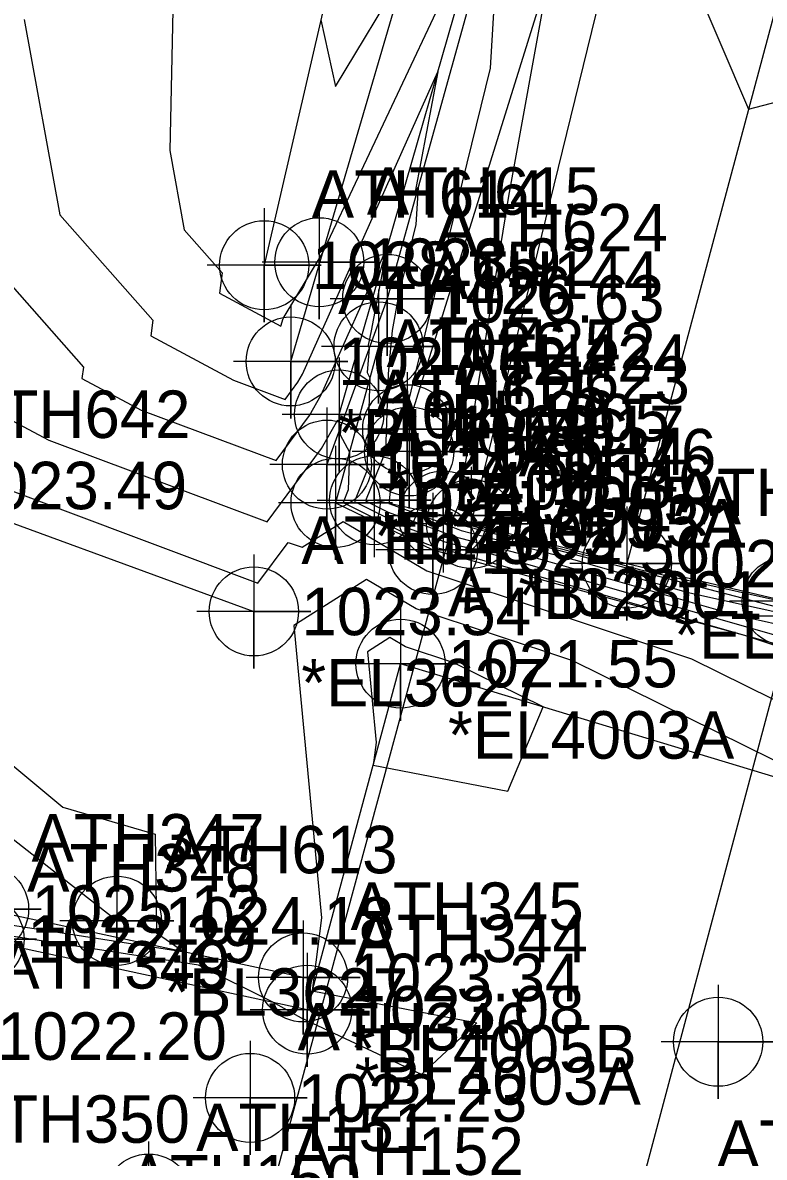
# Model space of a CAD drawing. Extents: x 1213164 to 1213550, y 766120 to 766870.
# Drawn here: x 1213304.4 to 1213343.4, y 766479.8 to 766539.5 of the extents above; entities that cross this region are included whole.
import ezdxf

# ---------------------------------------------------------------- set-up
doc = ezdxf.new("R2010")
doc.units = 0
for name, color, linetype in [('Default', 7, 'Continuous'), ('Exist DTM Breakline', 7, 'Continuous'), ('Exist DTM Breakline Cogo Comment', 7, 'Continuous'), ('Exist DTM Breakline Cogo Elevation', 7, 'Continuous'), ('Exist DTM Breakline Cogo Number', 7, 'Continuous'), ('Exist DTM Breakline Cogo Point CELL', 7, 'Continuous'), ('Exist DTM Crownline', 7, 'Continuous'), ('Exist DTM Crownline Cogo Comment', 7, 'Continuous'), ('Exist DTM Crownline Cogo Elevation', 7, 'Continuous'), ('Exist DTM Crownline Cogo Number', 7, 'Continuous'), ('Exist DTM Crownline Cogo Point CELL', 7, 'Continuous'), ('Exist DTM Drainline Cogo Comment', 7, 'Continuous'), ('Exist DTM Drainline Cogo Elevation', 7, 'Continuous'), ('Exist DTM Drainline Cogo Number', 7, 'Continuous'), ('Exist DTM Drainline Cogo Point CELL', 7, 'Continuous'), ('Exist DTM Regular Point Underwater CELL', 7, 'Continuous'), ('Exist DTM Regular Point Underwater Cogo Elevation', 7, 'Continuous'), ('Exist DTM Regular Point Underwater Cogo Number', 7, 'Continuous'), ('Exist Environmental Wetland Boundary Cogo Comment', 7, 'Continuous'), ('Exist Environmental Wetland Boundary Cogo Elevation', 7, 'Continuous'), ('Exist Environmental Wetland Boundary Cogo Number', 7, 'Continuous'), ('Exist Environmental Wetland Boundary Cogo Point CELL', 7, 'Continuous'), ('Exist Hydro Stream or Body of Water', 7, 'Continuous'), ('Exist Roads EOP', 7, 'Continuous'), ('Exist Roads EOP Cogo Comment', 7, 'Continuous'), ('Exist Roads EOP Cogo Elevation', 7, 'Continuous'), ('Exist Roads EOP Cogo Number', 7, 'Continuous'), ('Exist Roads EOP Cogo Point CELL', 7, 'Continuous'), ('Exist Structure Major Bridge WW Cogo Point CELL', 7, 'Continuous'), ('Exist Structure Major Deck Tunnel Box Culvert', 7, 'Continuous')]:
    doc.layers.add(name, color=color, linetype=linetype)

msp = doc.modelspace()

# ---------------------------------------------------------------- linework, layer by layer
at = {"layer": 'Default'}
for points in [[(1213312.606, 766556.566), (1213312.101, 766532.787), (1213312.865, 766528.603), (1213314.862, 766526.342), (1213314.71, 766525.28), (1213317.951, 766523.549), (1213318.074, 766523.952), (1213320.124, 766527.347), (1213326.276, 766540.392)], [(1213338.026, 766545.563), (1213342.554, 766534.959), (1213352.005, 766537.439), (1213352.534, 766537.592), (1213352.635, 766537.795), (1213353.026, 766538.706), (1213360.065, 766554.633)], [(1213332.007, 766541.892), (1213329.931, 766530.39), (1213327.288, 766514.12), (1213327, 766513.422), (1213327.863, 766513.073), (1213335.576, 766511.086), (1213336.81, 766510.732), (1213344.6, 766509), (1213344.738, 766508.974), (1213344.969, 766509.109), (1213352.579, 766524.276), (1213353.118, 766525.201), (1213353.296, 766525.429), (1213353.142, 766525.661), (1213361.519, 766549.652)], [(1213329.521, 766546.518), (1213328.953, 766537.116), (1213324.533, 766519.114), (1213324.485, 766518.851), (1213324.455, 766518.529), (1213324.436, 766517.95), (1213323.889, 766516.593), (1213323.629, 766514.207), (1213326.375, 766513.206), (1213327.431, 766512.78), (1213333.408, 766511.239), (1213339.3, 766509.55), (1213345.088, 766508.264), (1213346.155, 766508.062), (1213347.253, 766507.894), (1213348.774, 766508.818), (1213350.878, 766509.604), (1213350.411, 766509.881), (1213356.086, 766519.612), (1213359.141, 766523.529), (1213356.49, 766527.5), (1213362.202, 766543.858)], [(1213320.053, 766539.664), (1213320.823, 766536.156), (1213324.495, 766542.241)], [(1213304.44, 766539.672), (1213306.316, 766529.407), (1213311.215, 766523.86), (1213311.097, 766523.033), (1213315.452, 766520.706), (1213318.168, 766519.688), (1213318.845, 766520.601), (1213319.079, 766521.012), (1213326.207, 766536.928), (1213325.007, 766530.61), (1213325.17, 766530.84), (1213325.052, 766528.892), (1213324.137, 766525.162), (1213323.799, 766523.309), (1213323.589, 766521.031), (1213323.455, 766516.943), (1213322.408, 766514.347), (1213323.588, 766513.758), (1213326.249, 766512.788), (1213326.998, 766512.486), (1213331.241, 766511.392), (1213341.791, 766508.368), (1213345.575, 766507.527)], [(1213299.767, 766530.211), (1213307.568, 766521.377), (1213307.483, 766520.786), (1213310.597, 766519.123), (1213317.694, 766516.463), (1213319.461, 766518.848), (1213320.073, 766519.922), (1213323.53, 766527.642), (1213322.704, 766523.294), (1213322.531, 766522.548), (1213322.601, 766522.383), (1213322.486, 766521.1), (1213322.634, 766520.829), (1213322.474, 766515.935), (1213321.817, 766514.308), (1213324.551, 766512.944), (1213326.123, 766512.37), (1213326.566, 766512.192), (1213329.073, 766511.545), (1213344.281, 766507.187)], [(1213302.238, 766492.24), (1213291.887, 766494.194), (1213280.351, 766496.799), (1213269.143, 766496.101), (1213258.434, 766495.354), (1213246.448, 766501.682), (1213231.43, 766508.485), (1213230.134, 766509.143), (1213229.018, 766509.648), (1213227.82, 766526.686), (1213231.745, 766525.976), (1213232.384, 766525.606), (1213255.391, 766521.519), (1213260.994, 766517.838), (1213268.066, 766515.14), (1213276.814, 766515.993), (1213284.275, 766516.118), (1213289.429, 766512.414), (1213289.748, 766512.148), (1213306.473, 766498.233), (1213311.338, 766496.807), (1213311.406, 766491.611), (1213312.871, 766490.604), (1213302.238, 766492.24)], [(1213303.87, 766518.54), (1213305.741, 766517.54), (1213317.218, 766513.237), (1213320.077, 766517.095), (1213320.94, 766518.61), (1213321.096, 766518.242), (1213321.058, 766517.826), (1213321.557, 766516.911), (1213321.492, 766514.928), (1213321.226, 766514.269), (1213325.513, 766512.129), (1213325.997, 766511.953), (1213326.133, 766511.898), (1213326.906, 766511.699), (1213342.392, 766507.26), (1213345.801, 766506.125), (1213346.659, 766505.701), (1213349.337, 766501.052), (1213351.669, 766499.048), (1213357.648, 766493.804), (1213369.246, 766482.036), (1213370.687, 766479.709)], [(1213300.885, 766515.957), (1213316.743, 766510.012), (1213318.331, 766512.154), (1213319.064, 766511.902), (1213321.218, 766513.267), (1213325.627, 766510.661), (1213339.551, 766506.025), (1213348.137, 766501.785), (1213349.431, 766499.539), (1213350.558, 766498.57), (1213361.343, 766489.111), (1213368.811, 766481.534), (1213374.658, 766472.092), (1213383.401, 766456.504), (1213384.24, 766453.245), (1213389.563, 766440.166), (1213389.659, 766438.461), (1213389.891, 766435.088), (1213390.675, 766420.964), (1213391.789, 766405.168), (1213396.624, 766394.628)], [(1213378.629, 766464.474), (1213368.376, 766481.032), (1213365.038, 766484.419), (1213350.897, 766496.821), (1213346.478, 766493.776), (1213348.434, 766498.453), (1213333.3, 766505.924), (1213325.062, 766508.667), (1213322.453, 766510.209), (1213318.62, 766507.782), (1213320.087, 766492.397), (1213319.595, 766488.556), (1213328.26, 766486.873), (1213325.345, 766484.153), (1213319.036, 766487.115), (1213317.521, 766487.959), (1213313.605, 766489.92), (1213302.155, 766491.681)], [(1213329.881, 766499.067), (1213331.739, 766503.509), (1213327.05, 766505.824), (1213324.497, 766506.674), (1213323.688, 766507.152), (1213322.501, 766506.4), (1213322.955, 766501.632), (1213322.803, 766500.442), (1213329.881, 766499.067)]]:
    msp.add_lwpolyline(points, dxfattribs=at)
at = {"layer": 'Exist DTM Breakline'}
msp.add_line((1213326.487, 766513.577), (1213322.857, 766514.377), dxfattribs=at)
for points in [[(1213233.323, 766620.634), (1213306.317, 766606.349), (1213329.347, 766592.96), (1213324.12, 766557.271), (1213317.07, 766526.747)], [(1213318.463, 766521.688), (1213327.406, 766552.16), (1213336.347, 766594.126)], [(1213340.32, 766592.831), (1213332.04, 766555.596), (1213323.543, 766524.976), (1213320.373, 766516.254)], [(1213321.009, 766518.895), (1213330.265, 766551.006), (1213340.105, 766593.056)], [(1213324.598, 766518.116), (1213334.42, 766549.638), (1213342.103, 766590.629)], [(1213323.087, 766522.479), (1213320.824, 766514.242), (1213325.941, 766511.767), (1213346.495, 766506.136), (1213349.294, 766501.74), (1213353.051, 766499.642)], [(1213319.115, 766489.266), (1213302.33, 766492.864), (1213279.67, 766497.667), (1213258.903, 766496.781), (1213229.457, 766510.311)]]:
    msp.add_lwpolyline(points, dxfattribs=at)
at = {"layer": 'Exist DTM Breakline Cogo Point CELL'}
for points in [[(1213317.07, 766529.747), (1213317.07, 766523.747), (1213317.07, 766526.747), (1213320.07, 766526.747), (1213314.07, 766526.747)], [(1213319.97, 766529.906), (1213319.97, 766523.906), (1213319.97, 766526.906), (1213322.97, 766526.906), (1213316.97, 766526.906)], [(1213323.543, 766527.976), (1213323.543, 766521.976), (1213323.543, 766524.976), (1213326.543, 766524.976), (1213320.543, 766524.976)], [(1213323.087, 766525.479), (1213323.087, 766519.479), (1213323.087, 766522.479), (1213326.087, 766522.479), (1213320.087, 766522.479)], [(1213318.463, 766524.688), (1213318.463, 766518.688), (1213318.463, 766521.688), (1213321.463, 766521.688), (1213315.463, 766521.688)], [(1213321.009, 766521.895), (1213321.009, 766515.895), (1213321.009, 766518.895), (1213324.009, 766518.895), (1213318.009, 766518.895)], [(1213324.598, 766521.116), (1213324.598, 766515.116), (1213324.598, 766518.116), (1213327.598, 766518.116), (1213321.598, 766518.116)], [(1213324.699, 766519.95), (1213324.699, 766513.95), (1213324.699, 766516.95), (1213327.699, 766516.95), (1213321.699, 766516.95)], [(1213320.373, 766519.254), (1213320.373, 766513.254), (1213320.373, 766516.254), (1213323.373, 766516.254), (1213317.373, 766516.254)], [(1213320.824, 766517.242), (1213320.824, 766511.242), (1213320.824, 766514.242), (1213323.824, 766514.242), (1213317.824, 766514.242)], [(1213325.941, 766514.767), (1213325.941, 766508.767), (1213325.941, 766511.767), (1213328.941, 766511.767), (1213322.941, 766511.767)], [(1213302.33, 766495.864), (1213302.33, 766489.864), (1213302.33, 766492.864), (1213305.33, 766492.864), (1213299.33, 766492.864)], [(1213319.115, 766492.266), (1213319.115, 766486.266), (1213319.115, 766489.266), (1213322.115, 766489.266), (1213316.115, 766489.266)], [(1213310.985, 766480.629), (1213310.985, 766474.629), (1213310.985, 766477.629), (1213313.985, 766477.629), (1213307.985, 766477.629)]]:
    msp.add_lwpolyline(points, dxfattribs=at)
for centre in [(1213317.07, 766526.747), (1213319.97, 766526.906), (1213323.543, 766524.976), (1213323.087, 766522.479), (1213318.463, 766521.688), (1213321.009, 766518.895), (1213324.598, 766518.116), (1213324.699, 766516.95), (1213320.373, 766516.254), (1213320.824, 766514.242), (1213325.941, 766511.767), (1213302.33, 766492.864), (1213319.115, 766489.266), (1213310.985, 766477.629)]:
    msp.add_circle(centre, 2.344, dxfattribs=at)
at = {"layer": 'Exist DTM Crownline'}
msp.add_lwpolyline([(1213369.874, 766637.44), (1213360.318, 766601.875), (1213348.565, 766557.408), (1213336.15, 766511.045)], dxfattribs=at)
at = {"layer": 'Exist DTM Crownline Cogo Point CELL'}
msp.add_lwpolyline([(1213336.15, 766514.045), (1213336.15, 766508.045), (1213336.15, 766511.045), (1213339.15, 766511.045), (1213333.15, 766511.045)], dxfattribs=at)
msp.add_circle((1213336.15, 766511.045), 2.344, dxfattribs=at)
at = {"layer": 'Exist DTM Drainline Cogo Point CELL'}
for points in [[(1213324.243, 766508.779), (1213324.243, 766502.779), (1213324.243, 766505.779), (1213327.243, 766505.779), (1213321.243, 766505.779)], [(1213302.096, 766494.285), (1213302.096, 766488.285), (1213302.096, 766491.285), (1213305.096, 766491.285), (1213299.096, 766491.285)], [(1213319.329, 766490.569), (1213319.329, 766484.569), (1213319.329, 766487.569), (1213322.329, 766487.569), (1213316.329, 766487.569)]]:
    msp.add_lwpolyline(points, dxfattribs=at)
for centre in [(1213324.243, 766505.779), (1213302.096, 766491.285), (1213319.329, 766487.569)]:
    msp.add_circle(centre, 2.344, dxfattribs=at)
at = {"layer": 'Exist DTM Regular Point Underwater CELL'}
for points in [[(1213340.957, 766488.883), (1213340.957, 766482.883), (1213340.957, 766485.883), (1213343.957, 766485.883), (1213337.957, 766485.883)], [(1213316.327, 766485.924), (1213316.327, 766479.924), (1213316.327, 766482.924), (1213319.327, 766482.924), (1213313.327, 766482.924)]]:
    msp.add_lwpolyline(points, dxfattribs=at)
for centre in [(1213340.957, 766485.883), (1213316.327, 766482.924)]:
    msp.add_circle(centre, 2.344, dxfattribs=at)
at = {"layer": 'Exist Environmental Wetland Boundary Cogo Point CELL'}
for points in [[(1213316.525, 766511.528), (1213316.525, 766505.528), (1213316.525, 766508.528), (1213319.525, 766508.528), (1213313.525, 766508.528)], [(1213309.319, 766495.246), (1213309.319, 766489.246), (1213309.319, 766492.246), (1213312.319, 766492.246), (1213306.319, 766492.246)]]:
    msp.add_lwpolyline(points, dxfattribs=at)
for centre in [(1213316.525, 766508.528), (1213309.319, 766492.246)]:
    msp.add_circle(centre, 2.344, dxfattribs=at)
at = {"layer": 'Exist Hydro Stream or Body of Water'}
msp.add_line((1213319.329, 766487.569), (1213324.243, 766505.779), dxfattribs=at)
for points in [[(1213231.611, 766558.456), (1213254.919, 766547.163), (1213282.877, 766532.283), (1213282.707, 766524.453), (1213298.428, 766515.156), (1213316.525, 766508.528)], [(1213309.319, 766492.246), (1213285.214, 766511.13), (1213261.681, 766524.754), (1213227.09, 766533.988)], [(1213319.329, 766487.569), (1213302.096, 766491.285), (1213281.341, 766495.538), (1213258.142, 766494.464), (1213228.572, 766508.974)], [(1213462.585, 766303.681), (1213457.242, 766280.725), (1213458.541, 766244.269), (1213446.982, 766261.332), (1213440.132, 766307.328), (1213429.645, 766367.831), (1213400.182, 766384.285), (1213389.875, 766405.51), (1213387.132, 766439.706), (1213382.822, 766456.43), (1213368.024, 766480.627), (1213349.519, 766498.124), (1213324.243, 766505.779)]]:
    msp.add_lwpolyline(points, dxfattribs=at)
at = {"layer": 'Exist Roads EOP'}
for points in [[(1213327.952, 766513.134), (1213339.553, 766560.471), (1213350.847, 766605.718), (1213360.678, 766641.433)], [(1213327.952, 766513.134), (1213336.15, 766511.045), (1213344.559, 766509.063)]]:
    msp.add_lwpolyline(points, dxfattribs=at)
at = {"layer": 'Exist Roads EOP Cogo Point CELL'}
for points in [[(1213327.952, 766516.134), (1213327.952, 766510.134), (1213327.952, 766513.134), (1213330.952, 766513.134), (1213324.952, 766513.134)], [(1213344.559, 766512.063), (1213344.559, 766506.063), (1213344.559, 766509.063), (1213347.559, 766509.063), (1213341.559, 766509.063)]]:
    msp.add_lwpolyline(points, dxfattribs=at)
for centre in [(1213327.952, 766513.134), (1213344.559, 766509.063)]:
    msp.add_circle(centre, 2.344, dxfattribs=at)
at = {"layer": 'Exist Structure Major Bridge WW Cogo Point CELL'}
for points in [[(1213319.857, 766514.377), (1213325.857, 766514.377), (1213322.857, 766514.377), (1213322.857, 766517.377), (1213322.857, 766511.377)], [(1213323.487, 766513.577), (1213329.487, 766513.577), (1213326.487, 766513.577), (1213326.487, 766516.577), (1213326.487, 766510.577)], [(1213343.114, 766508.293), (1213349.114, 766508.293), (1213346.114, 766508.293), (1213346.114, 766511.293), (1213346.114, 766505.293)]]:
    msp.add_lwpolyline(points, dxfattribs=at)
for centre in [(1213322.857, 766514.377), (1213326.487, 766513.577)]:
    msp.add_circle(centre, 2.344, dxfattribs=at)
at = {"layer": 'Exist Structure Major Deck Tunnel Box Culvert'}
msp.add_lwpolyline([(1213334.645, 766469.793), (1213316.583, 766474.725), (1213327.014, 766513.184), (1213344.974, 766508.526), (1213334.645, 766469.793)], dxfattribs=at)

# ---------------------------------------------------------------- texts
at = {"layer": 'Exist DTM Breakline Cogo Comment'}
for s, p in [('*BL4005', (1213325.587, 766517.479)), ('*BL4005C', (1213320.963, 766516.688)), ('*BL4005B', (1213323.509, 766513.895)), ('*BL4005A', (1213327.098, 766513.116)), ('*EL4005A', (1213327.199, 766511.95)), ('*EL4005', (1213322.873, 766511.254)), ('*BL4005B', (1213321.615, 766484.266))]:
    msp.add_text(s, height=2.5, dxfattribs=at).set_placement(p)
at = {"layer": 'Exist DTM Breakline Cogo Elevation'}
for s, p in [('1028.65', (1213319.57, 766525.497)), ('1028.92', (1213322.47, 766525.656)), ('1026.63', (1213326.043, 766523.726)), ('1026.42', (1213325.587, 766521.229)), ('1027.62', (1213320.963, 766520.438)), ('1025.06', (1213323.509, 766517.645)), ('1028.17', (1213327.098, 766516.866)), ('1028.34', (1213327.199, 766515.7)), ('1024.52', (1213322.873, 766515.004)), ('1024.32', (1213323.324, 766512.992)), ('1024.56', (1213328.441, 766510.517)), ('1025.12', (1213304.83, 766491.614)), ('1023.34', (1213321.615, 766488.016))]:
    msp.add_text(s, height=2.5, dxfattribs=at).set_placement(p)
at = {"layer": 'Exist DTM Breakline Cogo Number'}
for s, p in [('ATH615', (1213322.47, 766529.406)), ('ATH614', (1213319.57, 766529.247)), ('ATH624', (1213326.043, 766527.476)), ('ATH144', (1213325.587, 766524.979)), ('ATH426', (1213320.963, 766524.188)), ('ATH425', (1213323.509, 766521.395)), ('ATH424', (1213327.098, 766520.616)), ('ATH623', (1213327.199, 766519.45)), ('ATH625', (1213322.873, 766518.754)), ('ATH145', (1213323.324, 766516.742)), ('ATH146', (1213328.441, 766514.267)), ('ATH347', (1213304.83, 766495.364)), ('ATH345', (1213321.615, 766491.766)), ('ATH151', (1213313.485, 766480.129)), ('ATH152', (1213318.462, 766478.873)), ('ATH150', (1213309.883, 766477.413))]:
    msp.add_text(s, height=2.5, dxfattribs=at).set_placement(p)
at = {"layer": 'Exist DTM Crownline Cogo Comment'}
msp.add_text('*EL3008', height=2.5, dxfattribs=at).set_placement((1213338.65, 766506.045))
at = {"layer": 'Exist DTM Crownline Cogo Elevation'}
msp.add_text('1029.27', height=2.5, dxfattribs=at).set_placement((1213338.65, 766509.795))
at = {"layer": 'Exist DTM Crownline Cogo Number'}
msp.add_text('ATH106', height=2.5, dxfattribs=at).set_placement((1213338.65, 766513.545))
at = {"layer": 'Exist DTM Drainline Cogo Comment'}
for s, p in [('*EL4003A', (1213326.743, 766500.779)), ('*BL4003A', (1213321.829, 766482.569))]:
    msp.add_text(s, height=2.5, dxfattribs=at).set_placement(p)
at = {"layer": 'Exist DTM Drainline Cogo Elevation'}
for s, p in [('1021.55', (1213326.743, 766504.529)), ('1022.29', (1213304.596, 766490.035)), ('1023.08', (1213321.829, 766486.319))]:
    msp.add_text(s, height=2.5, dxfattribs=at).set_placement(p)
at = {"layer": 'Exist DTM Drainline Cogo Number'}
for s, p in [('ATH328', (1213326.743, 766508.279)), ('ATH348', (1213304.596, 766493.785)), ('ATH344', (1213321.829, 766490.069)), ('ATH350', (1213300.896, 766480.565))]:
    msp.add_text(s, height=2.5, dxfattribs=at).set_placement(p)
at = {"layer": 'Exist DTM Regular Point Underwater Cogo Elevation'}
for s, p in [('1022.20', (1213303.023, 766484.928)), ('1022.23', (1213318.827, 766481.674))]:
    msp.add_text(s, height=2.5, dxfattribs=at).set_placement(p)
at = {"layer": 'Exist DTM Regular Point Underwater Cogo Number'}
for s, p in [('ATH349', (1213303.023, 766488.678)), ('ATH346', (1213318.827, 766485.424)), ('ATH324', (1213340.892, 766479.244))]:
    msp.add_text(s, height=2.5, dxfattribs=at).set_placement(p)
at = {"layer": 'Exist Environmental Wetland Boundary Cogo Comment'}
for s, p in [('*EL3627', (1213319.025, 766503.528)), ('*BL3627', (1213311.819, 766487.246))]:
    msp.add_text(s, height=2.5, dxfattribs=at).set_placement(p)
at = {"layer": 'Exist Environmental Wetland Boundary Cogo Elevation'}
for s, p in [('1023.49', (1213300.928, 766513.906)), ('1023.54', (1213319.025, 766507.278)), ('1024.18', (1213311.819, 766490.996))]:
    msp.add_text(s, height=2.5, dxfattribs=at).set_placement(p)
at = {"layer": 'Exist Environmental Wetland Boundary Cogo Number'}
for s, p in [('ATH642', (1213300.928, 766517.656)), ('ATH645', (1213319.025, 766511.028)), ('ATH613', (1213311.819, 766494.746))]:
    msp.add_text(s, height=2.5, dxfattribs=at).set_placement(p)
at = {"layer": 'Exist Roads EOP Cogo Comment'}
msp.add_text('*BL3001', height=2.5, dxfattribs=at).set_placement((1213330.452, 766508.134))
at = {"layer": 'Exist Roads EOP Cogo Elevation'}
msp.add_text('1029.21', height=2.5, dxfattribs=at).set_placement((1213330.452, 766511.884))
at = {"layer": 'Exist Roads EOP Cogo Number'}
msp.add_text('ATH76', height=2.5, dxfattribs=at).set_placement((1213330.452, 766515.634))

doc.saveas('drawing.dxf')
